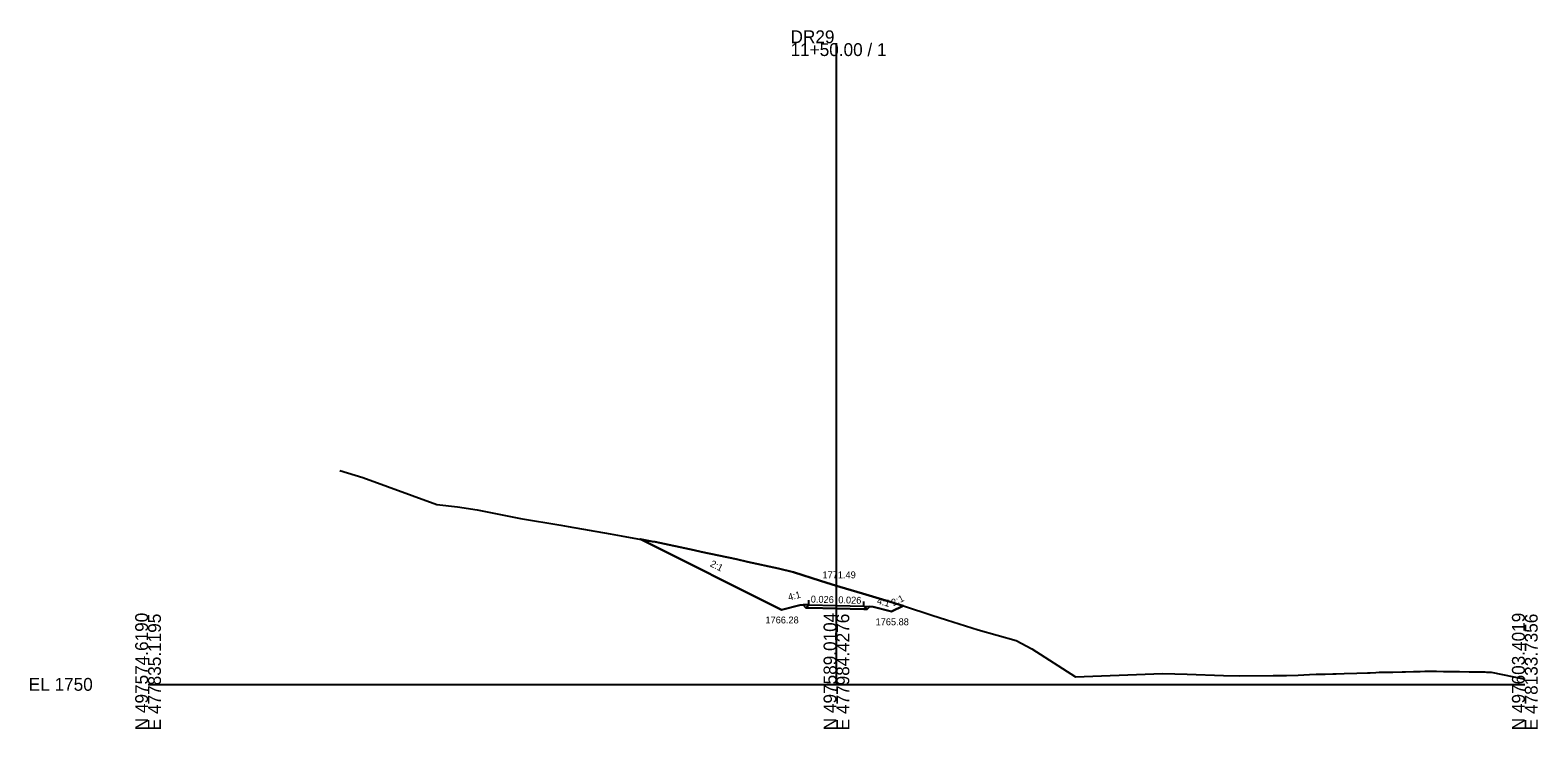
# Model space of a CAD drawing. Extents: x -26 to 303, y -10 to 4734.
# Drawn here: x -25.7 to 302.8, y 2990.3 to 3142.6 of the extents above; entities that cross this region are included whole.
import ezdxf

# ---------------------------------------------------------------- set-up
doc = ezdxf.new("R2010")
doc.units = 0
for name, color, linetype in [('Exist Cross Section Cell', 7, 'Continuous'), ('Exist XS Center Line Elevation Label', 7, 'Continuous'), ('Exist XS Ground Line', 7, 'Continuous'), ('Prop XS Ditch Slope Text', 7, 'Continuous'), ('Prop XS Ditch Standard Text', 7, 'Continuous'), ('Prop XS Dump Level', 7, 'Continuous'), ('Prop XS Earthwork Shape', 7, 'Continuous'), ('Prop XS EOT Tick Mark', 7, 'Continuous'), ('Prop XS Finish Grade', 7, 'Continuous'), ('Prop XS Finish Grade Earthwork', 7, 'Continuous'), ('Prop XS Finish Grade Pavement', 7, 'Continuous'), ('Prop XS Pvmt Edge Slope', 7, 'Continuous'), ('Prop XS SE Text', 7, 'Continuous'), ('Prop XS Shoulder Borrow Shape', 7, 'Continuous'), ('Prop XS Side Slope Text', 7, 'Continuous'), ('Prop XS Subgrade Earthwork', 7, 'Continuous')]:
    doc.layers.add(name, color=color, linetype=linetype)

msp = doc.modelspace()

# ---------------------------------------------------------------- linework, layer by layer
at = {"layer": 'Exist Cross Section Cell'}
for p, q in [((150, 3000), (150, 3139.73)), ((0, 3000), (150, 3000)), ((150, 3000), (300, 3000))]:
    msp.add_line(p, q, dxfattribs=at)
at = {"layer": 'Exist XS Ground Line'}
msp.add_lwpolyline([(41.77, 3046.58), (46.82, 3045.11), (62.94, 3039.18), (67.41, 3038.71), (71.69, 3038.01), (73.54, 3037.67), (81.18, 3036.16), (89.96, 3034.69), (91.53, 3034.44), (100.69, 3032.81), (103.06, 3032.39), (109.86, 3031.17), (110.51, 3031.05), (119.02, 3029.25), (120.56, 3028.92), (128.19, 3027.25), (130.61, 3026.7), (137.35, 3025.24), (140.66, 3024.47), (146.52, 3022.57), (150, 3021.49), (150.71, 3021.27), (155.68, 3019.8), (160.76, 3018.29), (164.85, 3017.06), (170.8, 3015.1), (174.01, 3014.05), (180.85, 3011.91), (189.15, 3009.57), (192.56, 3007.75), (202.12, 3001.64), (219.15, 3002.29), (221.04, 3002.38), (226.44, 3002.22), (234.32, 3001.9), (237.89, 3001.87), (245.16, 3001.93), (248.06, 3001.95), (250.63, 3001.97), (253.11, 3002.15), (254.53, 3002.19), (255.6, 3002.22), (256.47, 3002.25), (258.15, 3002.29), (258.89, 3002.31), (260.65, 3002.35), (263.41, 3002.41), (265.7, 3002.5), (266.33, 3002.53), (267.54, 3002.59), (268.23, 3002.63), (269.31, 3002.65), (270.75, 3002.67), (271.23, 3002.68), (273.24, 3002.74), (273.98, 3002.76), (275.74, 3002.81), (277.18, 3002.84), (278.24, 3002.87), (279.35, 3002.89), (280.02, 3002.9), (280.75, 3002.88), (282.3, 3002.84), (283.27, 3002.82), (285.09, 3002.8), (285.79, 3002.79), (287.89, 3002.74), (288.31, 3002.73), (288.73, 3002.73), (290.72, 3002.71), (291.28, 3002.7), (291.66, 3002.69), (292.68, 3002.66), (297.62, 3001.63), (300, 3001.12)], dxfattribs=at)
at = {"layer": 'Prop XS Dump Level'}
for p, q in [((144, 3017.35), (150, 3017.2)), ((150, 3017.2), (156, 3017.04))]:
    msp.add_line(p, q, dxfattribs=at)
at = {"layer": 'Prop XS Earthwork Shape'}
for points in [[(156, 3016.38), (150, 3016.53), (144, 3016.69), (143.35, 3016.7), (142.74, 3017.31), (142, 3017.28), (138, 3016.28), (107.32, 3031.63), (109.86, 3031.17), (110.51, 3031.05), (119.02, 3029.25), (120.56, 3028.92), (128.19, 3027.25), (130.61, 3026.7), (137.35, 3025.24), (140.66, 3024.47), (146.52, 3022.57), (150, 3021.49), (150.71, 3021.27), (155.68, 3019.8), (160.76, 3018.29), (164.55, 3017.15), (162, 3015.88), (158, 3016.88), (157.27, 3016.94), (156.68, 3016.36)], [(156.68, 3016.36), (157.27, 3016.94), (158, 3016.88), (162, 3015.88), (164.55, 3017.15), (160.76, 3018.29), (155.68, 3019.8), (150.71, 3021.27), (150, 3021.49), (146.52, 3022.57), (140.66, 3024.47), (137.35, 3025.24), (130.61, 3026.7), (128.19, 3027.25), (120.56, 3028.92), (119.02, 3029.25), (110.51, 3031.05), (109.86, 3031.17), (107.32, 3031.63), (138, 3016.28), (142, 3017.28), (142.74, 3017.31), (143.35, 3016.7), (144, 3016.69), (150, 3016.53), (156, 3016.38)]]:
    msp.add_lwpolyline(points, close=True, dxfattribs=at)
at = {"layer": 'Prop XS EOT Tick Mark'}
for p, q in [((144, 3017.35), (144, 3018.35)), ((156, 3017.04), (156, 3018.04))]:
    msp.add_line(p, q, dxfattribs=at)
at = {"layer": 'Prop XS Finish Grade'}
for p, q in [((144, 3017.35), (142.74, 3017.31)), ((156, 3017.04), (157.27, 3016.94))]:
    msp.add_line(p, q, dxfattribs=at)
at = {"layer": 'Prop XS Finish Grade Earthwork'}
for p, q in [((138, 3016.28), (107.32, 3031.63)), ((142, 3017.28), (138, 3016.28)), ((142.74, 3017.31), (142, 3017.28)), ((157.27, 3016.94), (158, 3016.88)), ((158, 3016.88), (162, 3015.88)), ((162, 3015.88), (164.55, 3017.15))]:
    msp.add_line(p, q, dxfattribs=at)
at = {"layer": 'Prop XS Finish Grade Pavement'}
for p, q in [((144, 3017.35), (150, 3017.2)), ((150, 3017.2), (156, 3017.04))]:
    msp.add_line(p, q, dxfattribs=at)
at = {"layer": 'Prop XS Pvmt Edge Slope'}
for p, q in [((144, 3017.35), (143.35, 3016.7)), ((156, 3017.04), (156.68, 3016.36))]:
    msp.add_line(p, q, dxfattribs=at)
at = {"layer": 'Prop XS Shoulder Borrow Shape'}
for points in [[(144, 3017.35), (142.74, 3017.31), (143.35, 3016.7)], [(156, 3017.04), (157.27, 3016.94), (156.68, 3016.36)]]:
    msp.add_lwpolyline(points, close=True, dxfattribs=at)
at = {"layer": 'Prop XS Subgrade Earthwork'}
for p, q in [((143.35, 3016.7), (142.74, 3017.31)), ((144, 3016.69), (143.35, 3016.7)), ((150, 3016.53), (144, 3016.69)), ((156, 3016.38), (150, 3016.53)), ((156, 3016.38), (156.68, 3016.36)), ((156.68, 3016.36), (157.27, 3016.94))]:
    msp.add_line(p, q, dxfattribs=at)

# ---------------------------------------------------------------- texts
at = {"layer": 'Exist Cross Section Cell'}
for s, p in [('DR29', (140, 3139.73)), ('11+50.00 / 1', (140, 3136.93)), ('EL 1750', (-26, 2998.6))]:
    msp.add_text(s, height=2.8, dxfattribs=at).set_placement(p)
for s, p in [('N 497574.6190', (0, 2990)), ('E 477835.1195', (2.8, 2990)), ('N 497589.0104', (150, 2990)), ('E 477984.4276', (152.8, 2990)), ('N 497603.4019', (300, 2990)), ('E 478133.7356', (302.8, 2990))]:
    msp.add_text(s, height=2.8, rotation=90, dxfattribs=at).set_placement(p)
at = {"layer": 'Exist XS Center Line Elevation Label'}
msp.add_text('1771.49', height=1.5, dxfattribs=at).set_placement((146.96, 3023.12))
at = {"layer": 'Prop XS Ditch Slope Text'}
for rotation, p in [(14.0362, (139.64, 3018.24)), (345.9638, (158.72, 3017.55))]:
    msp.add_text('4:1', height=1.5, rotation=rotation, dxfattribs=at).set_placement(p)
at = {"layer": 'Prop XS Ditch Standard Text'}
for s, p in [('1766.28', (134.53, 3013.28)), ('1765.88', (158.53, 3012.88))]:
    msp.add_text(s, height=1.5, dxfattribs=at).set_placement(p)
at = {"layer": 'Prop XS Dump Level'}
for p in [(142, 3017.24), (158, 3016.84)]:
    msp.add_text('Case1', height=0.04, dxfattribs=at).set_placement(p)
at = {"layer": 'Prop XS SE Text'}
for p in [(144.39, 3017.84), (150.39, 3017.69)]:
    msp.add_text('0.026', height=1.5, rotation=358.5152, dxfattribs=at).set_placement(p)
at = {"layer": 'Prop XS Side Slope Text'}
for rotation, p in [(333.4349, (122.32, 3025.8)), (26.5651, (162.41, 3017.02))]:
    msp.add_text('2:1', height=1.5, rotation=rotation, dxfattribs=at).set_placement(p)

doc.saveas('drawing.dxf')
